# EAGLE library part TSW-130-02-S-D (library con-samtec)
THROUGH-HOLE .025" SQ POST HEADER Source: Samtec TSW.pdf
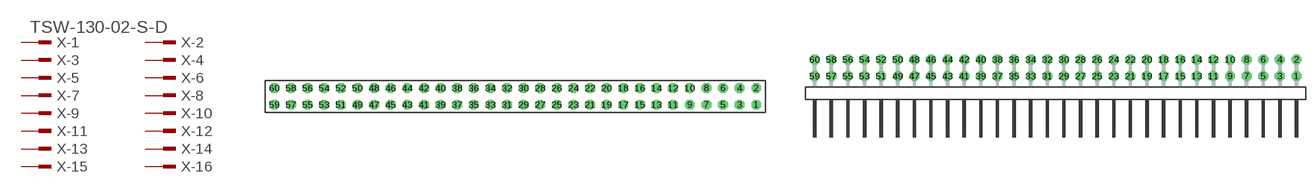
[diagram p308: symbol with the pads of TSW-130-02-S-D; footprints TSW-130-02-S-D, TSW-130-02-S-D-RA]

Designator prefix X; gates -1=MPINV -2=MPIN -3=MPIN -4=MPIN -5=MPIN -6=MPIN -7=MPIN -8=MPIN -9=MPIN -10=MPIN -11=MPIN -12=MPIN -13=MPIN -14=MPIN -15=MPIN -16=MPIN -17=MPIN -18=MPIN -19=MPIN -20=MPIN -21=MPIN -22=MPIN -23=MPIN -24=MPIN -25=MPIN -26=MPIN -27=MPIN -28=MPIN -29=MPIN -30=MPIN -31=MPIN -32=MPIN -33=MPIN -34=MPIN -35=MPIN -36=MPIN -37=MPIN -38=MPIN -39=MPIN -40=MPIN -41=MPIN -42=MPIN -43=MPIN -44=MPIN -45=MPIN -46=MPIN -47=MPIN -48=MPIN -49=MPIN -50=MPIN -51=MPIN -52=MPIN -53=MPIN -54=MPIN -55=MPIN -56=MPIN -57=MPIN -58=MPIN -59=MPIN -60=MPIN

## TSW-130-02-S-D (OC_FARNELL: unknown; OC_NEWARK: unknown)  [TSW-130-02-S-D]
1  -1:1  pas
2  -2:1  pas
3  -3:1  pas
4  -4:1  pas
5  -5:1  pas
6  -6:1  pas
7  -7:1  pas
8  -8:1  pas
9  -9:1  pas
10  -10:1  pas
11  -11:1  pas
12  -12:1  pas
13  -13:1  pas
14  -14:1  pas
15  -15:1  pas
16  -16:1  pas
17  -17:1  pas
18  -18:1  pas
19  -19:1  pas
20  -20:1  pas
21  -21:1  pas
22  -22:1  pas
23  -23:1  pas
24  -24:1  pas
25  -25:1  pas
26  -26:1  pas
27  -27:1  pas
28  -28:1  pas
29  -29:1  pas
30  -30:1  pas
31  -31:1  pas
32  -32:1  pas
33  -33:1  pas
34  -34:1  pas
35  -35:1  pas
36  -36:1  pas
37  -37:1  pas
38  -38:1  pas
39  -39:1  pas
40  -40:1  pas
41  -41:1  pas
42  -42:1  pas
43  -43:1  pas
44  -44:1  pas
45  -45:1  pas
46  -46:1  pas
47  -47:1  pas
48  -48:1  pas
49  -49:1  pas
50  -50:1  pas
51  -51:1  pas
52  -52:1  pas
53  -53:1  pas
54  -54:1  pas
55  -55:1  pas
56  -56:1  pas
57  -57:1  pas
58  -58:1  pas
59  -59:1  pas
60  -60:1  pas

## TSW-130-02-S-D-RA (OC_FARNELL: unknown; OC_NEWARK: unknown)  [TSW-130-02-S-D-RA]
Pads as for TSW-130-02-S-D

## Footprint TSW-130-02-S-D (pad centres in mm)
THROUGH-HOLE .025" SQ POST HEADER Source: Samtec TSW.pdf
drill 1 pad 1.5 octagon: 1 36.83,-1.27; 2 36.83,1.27; 3 34.29,-1.27; 4 34.29,1.27; 5 31.75,-1.27; 6 31.75,1.27; 7 29.21,-1.27; 8 29.21,1.27; 9 26.67,-1.27; 10 26.67,1.27; 11 24.13,-1.27; 12 24.13,1.27; 13 21.59,-1.27; 14 21.59,1.27; 15 19.05,-1.27; 16 19.05,1.27; 17 16.51,-1.27; 18 16.51,1.27; 19 13.97,-1.27; 20 13.97,1.27; 21 11.43,-1.27; 22 11.43,1.27; 23 8.89,-1.27; 24 8.89,1.27; 25 6.35,-1.27; 26 6.35,1.27; 27 3.81,-1.27; 28 3.81,1.27; 29 1.27,-1.27; 30 1.27,1.27; 31 -1.27,-1.27; 32 -1.27,1.27; 33 -3.81,-1.27; 34 -3.81,1.27; 35 -6.35,-1.27; 36 -6.35,1.27; 37 -8.89,-1.27; 38 -8.89,1.27; 39 -11.43,-1.27; 40 -11.43,1.27; 41 -13.97,-1.27; 42 -13.97,1.27; 43 -16.51,-1.27; 44 -16.51,1.27; 45 -19.05,-1.27; 46 -19.05,1.27; 47 -21.59,-1.27; 48 -21.59,1.27; 49 -24.13,-1.27; 50 -24.13,1.27; 51 -26.67,-1.27; 52 -26.67,1.27; 53 -29.21,-1.27; 54 -29.21,1.27; 55 -31.75,-1.27; 56 -31.75,1.27; 57 -34.29,-1.27; 58 -34.29,1.27; 59 -36.83,-1.27; 60 -36.83,1.27

## Footprint TSW-130-02-S-D-RA (pad centres in mm)
THROUGH-HOLE .025" SQ POST HEADER Source: Samtec TSW.pdf
drill 1 pad 1.5 octagon: 1 36.83,1.524; 2 36.83,4.064; 3 34.29,1.524; 4 34.29,4.064; 5 31.75,1.524; 6 31.75,4.064; 7 29.21,1.524; 8 29.21,4.064; 9 26.67,1.524; 10 26.67,4.064; 11 24.13,1.524; 12 24.13,4.064; 13 21.59,1.524; 14 21.59,4.064; 15 19.05,1.524; 16 19.05,4.064; 17 16.51,1.524; 18 16.51,4.064; 19 13.97,1.524; 20 13.97,4.064; 21 11.43,1.524; 22 11.43,4.064; 23 8.89,1.524; 24 8.89,4.064; 25 6.35,1.524; 26 6.35,4.064; 27 3.81,1.524; 28 3.81,4.064; 29 1.27,1.524; 30 1.27,4.064; 31 -1.27,1.524; 32 -1.27,4.064; 33 -3.81,1.524; 34 -3.81,4.064; 35 -6.35,1.524; 36 -6.35,4.064; 37 -8.89,1.524; 38 -8.89,4.064; 39 -11.43,1.524; 40 -11.43,4.064; 41 -13.97,1.524; 42 -13.97,4.064; 43 -16.51,1.524; 44 -16.51,4.064; 45 -19.05,1.524; 46 -19.05,4.064; 47 -21.59,1.524; 48 -21.59,4.064; 49 -24.13,1.524; 50 -24.13,4.064; 51 -26.67,1.524; 52 -26.67,4.064; 53 -29.21,1.524; 54 -29.21,4.064; 55 -31.75,1.524; 56 -31.75,4.064; 57 -34.29,1.524; 58 -34.29,4.064; 59 -36.83,1.524; 60 -36.83,4.064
